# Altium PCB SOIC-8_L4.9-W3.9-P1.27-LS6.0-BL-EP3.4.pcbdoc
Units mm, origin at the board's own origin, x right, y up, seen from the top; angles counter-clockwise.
Board outline 18.13 x 20.95 mm, 2 copper layers (Top Layer, Bottom Layer), stack 0 mm thick; 1 components, 0 nets, 9 pads, 0 vias.
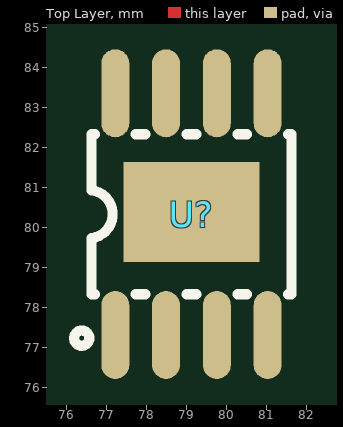
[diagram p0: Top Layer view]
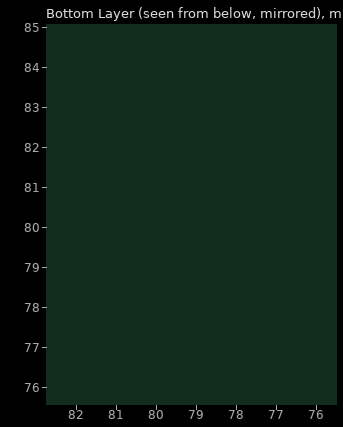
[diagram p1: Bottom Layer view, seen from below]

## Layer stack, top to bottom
Top Layer: signal copper (thickness not stored)
Bottom Layer: signal copper (thickness not stored)

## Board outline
87.984,69.85 69.85,69.85 69.85,90.795 87.984,90.795

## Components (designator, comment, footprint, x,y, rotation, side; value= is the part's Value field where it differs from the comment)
U? "" SOIC-8_L4.9-W3.9-P1.27-LS6.0-BL-EP3.4 79.134,80.323 r0 top

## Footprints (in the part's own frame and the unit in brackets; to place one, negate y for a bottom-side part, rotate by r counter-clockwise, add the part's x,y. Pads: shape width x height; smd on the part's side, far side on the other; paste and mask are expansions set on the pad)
SOIC-8_L4.9-W3.9-P1.27-LS6.0-BL-EP3.4 [mm]
  oval 0.7x2.2 smd paste+0 mask+0.05: 1(-1.905,-3.023) 2(-0.635,-3.023) 3(0.635,-3.023) 4(1.905,-3.023) 5(1.905,3.023) 6(0.635,3.023) 7(-0.635,3.023) 8(-1.905,3.023)
  rect 3.4x2.5 smd paste+0 mask+0.05: 9(0,0.051)
  silkscreen extent -2.93,-3.29 2.5,2

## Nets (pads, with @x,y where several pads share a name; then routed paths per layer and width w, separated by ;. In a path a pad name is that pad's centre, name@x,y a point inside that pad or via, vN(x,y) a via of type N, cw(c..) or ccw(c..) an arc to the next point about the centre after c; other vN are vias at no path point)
pads on no net: U?.1 U?.2 U?.3 U?.4 U?.5 U?.6 U?.7 U?.8 U?.9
